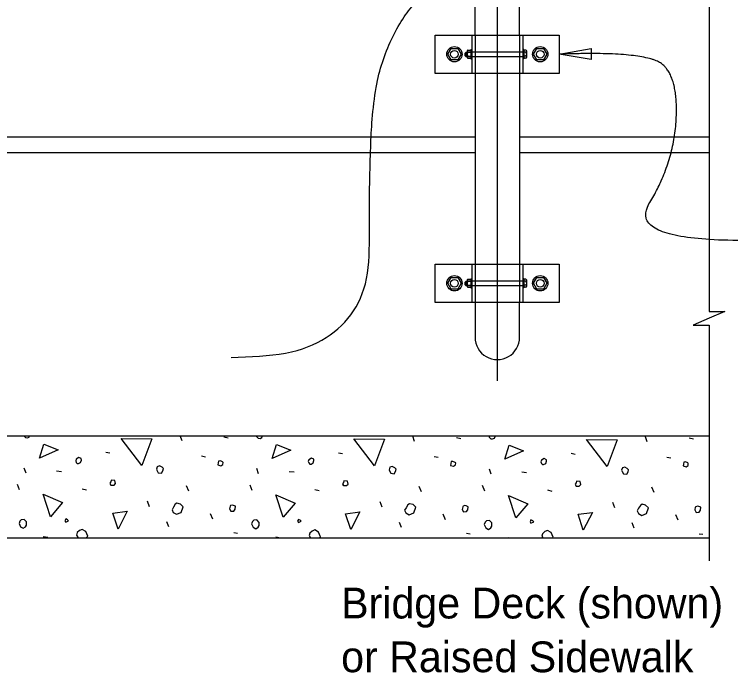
# Model space of a CAD drawing. Extents: x 0 to 41.2, y 0 to 26.
# Drawn here: x 19.043 to 23.735, y 12.919 to 17.231 of the extents above; entities that cross this region are included whole.
import ezdxf

# ---------------------------------------------------------------- set-up
doc = ezdxf.new("R2010")
doc.units = 0
for name, color, linetype in [('CL_Major', 7, 'Continuous'), ('Dimension', 7, 'Continuous'), ('Miscellaneous', 7, 'Continuous'), ('SteelMisc', 7, 'Continuous'), ('SteelMisc_h', 7, 'Continuous'), ('SupstrConc', 7, 'Continuous')]:
    doc.layers.add(name, color=color, linetype=linetype)

msp = doc.modelspace()

# ---------------------------------------------------------------- linework, layer by layer
at = {"layer": 'CL_Major'}
msp.add_line((22.2062, 25.6784), (22.2062, 14.8312), dxfattribs=at)
at = {"layer": 'Dimension'}
for points in [[(23.5932, 20.1983), (23.5932, 19.1806), (23.6966, 19.1806), (23.5932, 19.1356), (23.4899, 19.0906), (23.5932, 19.0906), (23.5932, 16.8862)], [(23.5932, 17.1362), (23.5932, 15.2854), (23.6966, 15.2854), (23.5932, 15.2404), (23.4899, 15.1954), (23.5932, 15.1954), (23.5932, 13.6529)]]:
    msp.add_lwpolyline(points, dxfattribs=at)
msp.add_lwpolyline([(22.8207, 16.9356), (22.6122, 16.9694), (22.8202, 17.0062)], close=True, dxfattribs=at)
for points in [[(20.4632, 14.9843), (21.3717, 14.9643), (21.3652, 16.4454), (21.4405, 16.9433), (21.6515, 17.3204), (21.8903, 17.4554), (21.9647, 17.4872), (22.0043, 17.5089), (21.982, 17.3708), (21.7151, 17.4193)], [(23.9932, 15.7529), (23.0399, 15.7236), (23.3618, 16.2556), (23.3935, 16.8155), (23.1813, 16.9916), (22.6122, 16.9694)]]:
    msp.add_open_spline(points, degree=2, dxfattribs=at)
at = {"layer": 'Miscellaneous'}
for p, q in [((21.9986, 16.9625), (21.9986, 16.9746)), ((22.0044, 16.9625), (22.0044, 16.9746)), ((21.9986, 15.4625), (21.9986, 15.4746)), ((22.0044, 15.4625), (22.0044, 15.4746)), ((20.141, 14.4376), (20.1292, 14.4695)), ((20.415, 14.4641), (20.4432, 14.4571)), ((21.6648, 14.4341), (21.6524, 14.4677)), ((21.9388, 14.4606), (21.9671, 14.4535)), ((23.1886, 14.4306), (23.1762, 14.4641)), ((23.4626, 14.4571), (23.4909, 14.45)), ((19.6424, 14.3634), (19.669, 14.3581)), ((21.1663, 14.3599), (21.1928, 14.3545)), ((20.2682, 14.3386), (20.2947, 14.3333)), ((21.792, 14.3351), (21.8186, 14.3298)), ((22.6901, 14.3563), (22.7166, 14.351)), ((23.3159, 14.3316), (23.3424, 14.3263)), ((19.1192, 14.2255), (19.1068, 14.2591)), ((19.3189, 14.2414), (19.3508, 14.2379)), ((20.643, 14.222), (20.6306, 14.2556)), ((20.8428, 14.2379), (20.8746, 14.2343)), ((22.1668, 14.2184), (22.1544, 14.252)), ((22.3666, 14.2343), (22.3984, 14.2308)), ((19.0768, 14.1159), (19.0626, 14.1513)), ((20.1851, 14.1071), (20.171, 14.1424)), ((20.6006, 14.1124), (20.5864, 14.1477)), ((21.709, 14.1035), (21.6948, 14.1389)), ((22.1244, 14.1088), (22.1102, 14.1442)), ((23.2328, 14.1), (23.2186, 14.1353)), ((19.4869, 14.123), (19.5152, 14.1159)), ((21.0107, 14.1194), (21.039, 14.1124)), ((22.5345, 14.1159), (22.5628, 14.1088)), ((19.9288, 14.0063), (19.9147, 14.0417)), ((21.4526, 14.0028), (21.4385, 14.0381)), ((22.9765, 13.9992), (22.9623, 14.0346)), ((20.3425, 13.925), (20.3283, 13.9603)), ((21.8663, 13.9214), (21.8522, 13.9568)), ((23.3901, 13.9179), (23.376, 13.9533)), ((20.0543, 13.8737), (20.042, 13.9073)), ((21.5781, 13.8702), (21.5658, 13.9038)), ((23.102, 13.8666), (23.0896, 13.9002)), ((19.2323, 13.8118), (19.2624, 13.8065)), ((20.4804, 13.8366), (20.5051, 13.8331)), ((20.7561, 13.8083), (20.7862, 13.803)), ((22.0042, 13.8331), (22.0289, 13.8295)), ((22.28, 13.8048), (22.2912, 13.8028)), ((23.528, 13.8295), (23.5527, 13.826))]:
    msp.add_line(p, q, dxfattribs=at)
for points in [[(19.105, 14.4695), (19.1156, 14.4588)], [(19.1156, 14.4588), (19.128, 14.4571), (19.1404, 14.4624), (19.1428, 14.4695)], [(19.8776, 14.2768), (19.7432, 14.4535), (19.943, 14.4518), (19.8776, 14.2768)], [(20.63, 14.4695), (20.6289, 14.4659), (20.6395, 14.4553)], [(20.6395, 14.4553), (20.6518, 14.4535), (20.6642, 14.4588), (20.6677, 14.4695)], [(22.155, 14.4695), (22.1527, 14.4624), (22.1633, 14.4518)], [(22.1633, 14.4518), (22.1757, 14.45), (22.188, 14.4553), (22.1916, 14.4659), (22.1894, 14.4695)], [(19.2076, 14.3245), (19.2359, 14.4164), (19.3295, 14.3793), (19.2076, 14.3245)], [(20.7314, 14.321), (20.7597, 14.4129), (20.8534, 14.3758), (20.7314, 14.321)], [(21.4014, 14.2732), (21.267, 14.45), (21.4668, 14.4482), (21.4014, 14.2732)], [(22.2552, 14.3174), (22.2835, 14.4093), (22.3772, 14.3722), (22.2552, 14.3174)], [(22.9252, 14.2697), (22.7908, 14.4465), (22.9906, 14.4447), (22.9252, 14.2697)], [(19.4551, 14.2891), (19.4621, 14.2891), (19.4763, 14.2962), (19.4816, 14.3121), (19.4798, 14.321), (19.4657, 14.328), (19.448, 14.3174), (19.4445, 14.3068), (19.448, 14.2962), (19.4551, 14.2891)], [(20.9789, 14.2856), (20.9859, 14.2856), (21.0001, 14.2927), (21.0054, 14.3086), (21.0036, 14.3174), (20.9895, 14.3245), (20.9718, 14.3139), (20.9683, 14.3033), (20.9718, 14.2927), (20.9789, 14.2856)], [(22.5027, 14.2821), (22.5098, 14.2821), (22.5239, 14.2891), (22.5292, 14.305), (22.5274, 14.3139), (22.5133, 14.321), (22.4956, 14.3104), (22.4921, 14.2997), (22.4956, 14.2891), (22.5027, 14.2821)], [(19.9766, 14.2449), (19.9854, 14.229), (20.0066, 14.2255), (20.0154, 14.2414), (20.019, 14.2556), (20.0101, 14.2644), (19.9942, 14.2732), (19.9783, 14.2679), (19.973, 14.252), (19.9766, 14.2449)], [(20.3761, 14.2803), (20.3955, 14.275), (20.4079, 14.2838), (20.4097, 14.2962), (20.4061, 14.2997), (20.392, 14.3068), (20.3796, 14.305), (20.3778, 14.2927), (20.3761, 14.2803)], [(21.5004, 14.2414), (21.5092, 14.2255), (21.5304, 14.222), (21.5393, 14.2379), (21.5428, 14.252), (21.534, 14.2609), (21.518, 14.2697), (21.5021, 14.2644), (21.4968, 14.2485), (21.5004, 14.2414)], [(21.8999, 14.2768), (21.9193, 14.2715), (21.9317, 14.2803), (21.9335, 14.2927), (21.9299, 14.2962), (21.9158, 14.3033), (21.9034, 14.3015), (21.9016, 14.2891), (21.8999, 14.2768)], [(23.0242, 14.2379), (23.033, 14.222), (23.0542, 14.2184), (23.0631, 14.2343), (23.0666, 14.2485), (23.0578, 14.2573), (23.0419, 14.2662), (23.0259, 14.2609), (23.0206, 14.2449), (23.0242, 14.2379)], [(23.4237, 14.2732), (23.4431, 14.2679), (23.4555, 14.2768), (23.4573, 14.2891), (23.4537, 14.2927), (23.4396, 14.2997), (23.4272, 14.298), (23.4255, 14.2856), (23.4237, 14.2732)], [(19.6743, 14.1477), (19.6955, 14.1477), (19.7061, 14.1583), (19.7008, 14.1778), (19.6778, 14.1795), (19.6743, 14.1689), (19.669, 14.1601), (19.6743, 14.1477), (19.6707, 14.1513)], [(21.1981, 14.1442), (21.2193, 14.1442), (21.2299, 14.1548), (21.2246, 14.1742), (21.2016, 14.176), (21.1981, 14.1654), (21.1928, 14.1566), (21.1981, 14.1442), (21.1945, 14.1477)], [(22.7219, 14.1406), (22.7431, 14.1406), (22.7537, 14.1513), (22.7484, 14.1707), (22.7254, 14.1725), (22.7219, 14.1619), (22.7166, 14.153), (22.7219, 14.1406), (22.7184, 14.1442)], [(19.2801, 13.9409), (19.2323, 14.0876), (19.3578, 14.0328), (19.2801, 13.9409)], [(20.8039, 13.9374), (20.7561, 14.0841), (20.8816, 14.0293), (20.8039, 13.9374)], [(22.3277, 13.9338), (22.28, 14.0805), (22.4055, 14.0257), (22.3277, 13.9338)], [(20.0826, 13.9692), (20.1056, 13.9568), (20.1356, 13.9692), (20.148, 14.0063), (20.1303, 14.024), (20.1074, 14.0293), (20.0968, 14.0222), (20.0844, 14.0028), (20.0755, 13.9869), (20.0826, 13.9692)], [(20.4521, 13.9922), (20.4609, 13.9762), (20.4804, 13.978), (20.4892, 13.9904), (20.491, 14.0098), (20.4786, 14.0151), (20.4698, 14.0169), (20.4592, 14.0134), (20.4556, 14.0098), (20.4521, 13.9922)], [(21.6064, 13.9656), (21.6294, 13.9533), (21.6595, 13.9656), (21.6718, 14.0028), (21.6542, 14.0204), (21.6312, 14.0257), (21.6206, 14.0187), (21.6082, 13.9992), (21.5994, 13.9833), (21.6064, 13.9656)], [(21.9759, 13.9886), (21.9847, 13.9727), (22.0042, 13.9745), (22.013, 13.9869), (22.0148, 14.0063), (22.0024, 14.0116), (21.9936, 14.0134), (21.983, 14.0098), (21.9794, 14.0063), (21.9759, 13.9886)], [(23.1302, 13.9621), (23.1532, 13.9497), (23.1833, 13.9621), (23.1957, 13.9992), (23.178, 14.0169), (23.155, 14.0222), (23.1444, 14.0151), (23.132, 13.9957), (23.1232, 13.9798), (23.1302, 13.9621)], [(23.4997, 13.9851), (23.5085, 13.9692), (23.528, 13.9709), (23.5368, 13.9833), (23.5386, 14.0028), (23.5262, 14.0081), (23.5174, 14.0098), (23.5068, 14.0063), (23.5032, 14.0028), (23.4997, 13.9851)], [(19.722, 13.8596), (19.6884, 13.9639), (19.7821, 13.9762), (19.722, 13.8596)], [(21.2458, 13.856), (21.2122, 13.9603), (21.3059, 13.9727), (21.2458, 13.856)], [(22.7696, 13.8525), (22.736, 13.9568), (22.8297, 13.9692), (22.7696, 13.8525)], [(19.0732, 13.8967), (19.0838, 13.8755), (19.1015, 13.8649), (19.1156, 13.8755), (19.1227, 13.8861), (19.1227, 13.9073), (19.1068, 13.9232), (19.0874, 13.9214), (19.0785, 13.9126), (19.0732, 13.8967)], [(19.379, 13.9055), (19.3985, 13.9144), (19.3914, 13.9214), (19.379, 13.9267), (19.3737, 13.9144), (19.379, 13.9055)], [(20.597, 13.8932), (20.6076, 13.8719), (20.6253, 13.8613), (20.6395, 13.8719), (20.6465, 13.8826), (20.6465, 13.9038), (20.6306, 13.9197), (20.6112, 13.9179), (20.6023, 13.9091), (20.597, 13.8932)], [(20.9029, 13.902), (20.9223, 13.9108), (20.9152, 13.9179), (20.9029, 13.9232), (20.8976, 13.9108), (20.9029, 13.902)], [(22.1209, 13.8896), (22.1315, 13.8684), (22.1491, 13.8578), (22.1633, 13.8684), (22.1703, 13.879), (22.1703, 13.9002), (22.1544, 13.9161), (22.135, 13.9144), (22.1262, 13.9055), (22.1209, 13.8896)], [(22.4267, 13.8985), (22.4461, 13.9073), (22.4391, 13.9144), (22.4267, 13.9197), (22.4214, 13.9073), (22.4267, 13.8985)], [(19.5132, 13.8028), (19.524, 13.8136), (19.5116, 13.8437), (19.4869, 13.8578), (19.4692, 13.8507), (19.4551, 13.8366), (19.4498, 13.8207)], [(21.0405, 13.8028), (21.0478, 13.8101), (21.0354, 13.8401), (21.0107, 13.8543), (20.993, 13.8472), (20.9789, 13.8331), (20.9736, 13.8171)], [(22.5679, 13.8028), (22.5716, 13.8065), (22.5593, 13.8366), (22.5345, 13.8507), (22.5168, 13.8437), (22.5027, 13.8295), (22.4974, 13.8136)], [(19.4498, 13.8207), (19.4608, 13.8028)], [(20.9736, 13.8171), (20.9825, 13.8028)], [(22.4974, 13.8136), (22.5041, 13.8028)]]:
    msp.add_lwpolyline(points, dxfattribs=at)
at = {"layer": 'SteelMisc'}
for p, q in [((22.0604, 17.0944), (22.0604, 17.7968)), ((22.3521, 17.0944), (22.3521, 17.7968)), ((21.8002, 17.0944), (22.6122, 17.0944)), ((21.8002, 16.8444), (21.8002, 17.0944)), ((22.0396, 17.0944), (22.0396, 16.8444)), ((22.3729, 17.0944), (22.3729, 16.8444)), ((22.6122, 17.0944), (22.6122, 16.8444)), ((22.008, 16.9873), (22.008, 16.9516)), ((22.0129, 16.9954), (22.033, 16.9954)), ((22.033, 16.9997), (22.033, 16.9391)), ((22.033, 16.9997), (22.0396, 16.9997)), ((22.033, 16.9954), (22.033, 16.9435)), ((22.3792, 16.9997), (22.3731, 16.9997)), ((22.3939, 16.9954), (22.3791, 16.9954)), ((22.3792, 16.9997), (22.3792, 16.9391)), ((22.399, 16.95), (22.399, 16.9889)), ((21.9958, 16.9774), (22.0015, 16.984)), ((21.9958, 16.9597), (21.9958, 16.9774)), ((21.9958, 16.9597), (22.0015, 16.9541)), ((22.0015, 16.984), (22.008, 16.984)), ((22.0015, 16.9541), (22.0015, 16.984)), ((22.0015, 16.9541), (22.008, 16.9541)), ((22.0127, 16.9824), (22.033, 16.9824)), ((22.0127, 16.9565), (22.033, 16.9565)), ((22.013, 16.9435), (22.033, 16.9435)), ((22.033, 16.9391), (22.0396, 16.9391)), ((22.3792, 16.9391), (22.3731, 16.9391)), ((22.394, 16.9824), (22.3791, 16.9824)), ((22.394, 16.9564), (22.3791, 16.9564)), ((22.3939, 16.9434), (22.3791, 16.9434)), ((22.6122, 16.8444), (21.8002, 16.8444)), ((22.0604, 16.8444), (22.0604, 15.5944)), ((22.3521, 16.8444), (22.3521, 15.5944)), ((21.8002, 15.5944), (22.6122, 15.5944)), ((21.8002, 15.3444), (21.8002, 15.5944)), ((22.0396, 15.5944), (22.0396, 15.3444)), ((22.3729, 15.5944), (22.3729, 15.3444)), ((22.6122, 15.5944), (22.6122, 15.3444)), ((22.008, 15.4873), (22.008, 15.4516)), ((22.0129, 15.4954), (22.033, 15.4954)), ((22.033, 15.4997), (22.033, 15.4391)), ((22.033, 15.4997), (22.0396, 15.4997)), ((22.033, 15.4954), (22.033, 15.4435)), ((22.3792, 15.4997), (22.3731, 15.4997)), ((22.3939, 15.4954), (22.3791, 15.4954)), ((22.3792, 15.4997), (22.3792, 15.4391)), ((22.399, 15.45), (22.399, 15.4889)), ((21.9958, 15.4774), (22.0015, 15.484)), ((21.9958, 15.4597), (21.9958, 15.4774)), ((21.9958, 15.4597), (22.0015, 15.4541)), ((22.0015, 15.484), (22.008, 15.484)), ((22.0015, 15.4541), (22.0015, 15.484)), ((22.0015, 15.4541), (22.008, 15.4541)), ((22.0127, 15.4824), (22.033, 15.4824)), ((22.0127, 15.4565), (22.033, 15.4565)), ((22.013, 15.4435), (22.033, 15.4435)), ((22.033, 15.4391), (22.0396, 15.4391)), ((22.3792, 15.4391), (22.3731, 15.4391)), ((22.394, 15.4824), (22.3791, 15.4824)), ((22.394, 15.4564), (22.3791, 15.4564)), ((22.3939, 15.4434), (22.3791, 15.4434)), ((22.6122, 15.3444), (21.8002, 15.3444)), ((22.0603, 15.3444), (22.0603, 15.1153)), ((22.3519, 15.1153), (22.3519, 15.3444))]:
    msp.add_line(p, q, dxfattribs=at)
for points in [[(21.9036, 17.007), (21.9469, 17.007), (21.9686, 16.9694), (21.9469, 16.9319), (21.9036, 16.9319), (21.8819, 16.9694)], [(22.4655, 17.007), (22.5089, 17.007), (22.5305, 16.9694), (22.5089, 16.9319), (22.4655, 16.9319), (22.4439, 16.9694)], [(21.9036, 15.507), (21.9469, 15.507), (21.9686, 15.4694), (21.9469, 15.4319), (21.9036, 15.4319), (21.8819, 15.4694)], [(22.4655, 15.507), (22.5089, 15.507), (22.5305, 15.4694), (22.5089, 15.4319), (22.4655, 15.4319), (22.4439, 15.4694)]]:
    msp.add_lwpolyline(points, close=True, dxfattribs=at)
for centre, radius in [((21.9252, 16.9694), 0.05), ((21.9252, 16.9694), 0.025), ((22.4872, 16.9694), 0.05), ((22.4872, 16.9694), 0.025), ((21.9252, 15.4694), 0.05), ((21.9252, 15.4694), 0.025), ((22.4872, 15.4694), 0.05), ((22.4872, 15.4694), 0.025)]:
    msp.add_circle(centre, radius, dxfattribs=at)
for centre, radius, start, end in [((22.0145, 16.9889), 0.00674, 104.4891, 254.1889), ((22.3922, 16.9889), 0.00673, 285.7823, 75.5404), ((22.0274, 16.9694), 0.0196, 138.628, 221.372), ((22.0145, 16.95), 0.00673, 105.7823, 255.5404), ((22.3922, 16.95), 0.00674, 284.4891, 74.1889), ((22.3793, 16.9694), 0.0196, 318.628, 41.372), ((22.0145, 15.4889), 0.00674, 104.4891, 254.1889), ((22.3922, 15.4889), 0.00673, 285.7823, 75.5404), ((22.0274, 15.4694), 0.0196, 138.628, 221.372), ((22.0145, 15.45), 0.00673, 105.7823, 255.5404), ((22.3922, 15.45), 0.00674, 284.4891, 74.1889), ((22.3793, 15.4694), 0.0196, 318.628, 41.372)]:
    msp.add_arc(centre, radius, start, end, dxfattribs=at)
msp.add_ellipse((22.2062, 15.1153), major_axis=(0, 0.1458), ratio=0.999499, start_param=1.570796, end_param=4.712389, dxfattribs=at)
at = {"layer": 'SteelMisc_h'}
for p, q in [((22.0604, 17.0944), (22.0604, 16.8444)), ((22.3521, 17.0944), (22.3521, 16.8444)), ((22.3729, 16.984), (22.008, 16.984)), ((22.008, 16.9541), (22.3729, 16.9541)), ((22.0604, 15.5944), (22.0604, 15.3444)), ((22.3521, 15.5944), (22.3521, 15.3444)), ((22.3729, 15.484), (22.008, 15.484)), ((22.008, 15.4541), (22.3729, 15.4541))]:
    msp.add_line(p, q, dxfattribs=at)
at = {"layer": 'SupstrConc'}
for p, q in [((12.3521, 16.4295), (22.0604, 16.4295)), ((22.3521, 16.4295), (23.5931, 16.4295)), ((12.3521, 16.3254), (22.0604, 16.3254)), ((22.3521, 16.3254), (23.5931, 16.3254)), ((0.8193, 14.4695), (23.5931, 14.4695)), ((0.8193, 13.8028), (23.5931, 13.8028))]:
    msp.add_line(p, q, dxfattribs=at)

# ---------------------------------------------------------------- texts
at = {"layer": 'Dimension'}
for s, p in [('Bridge Deck (shown)', (21.1833, 13.2743)), ('or Raised Sidewalk', (21.1833, 12.9223))]:
    msp.add_text(s, height=0.2016, dxfattribs=at).set_placement(p)

doc.saveas('drawing.dxf')
